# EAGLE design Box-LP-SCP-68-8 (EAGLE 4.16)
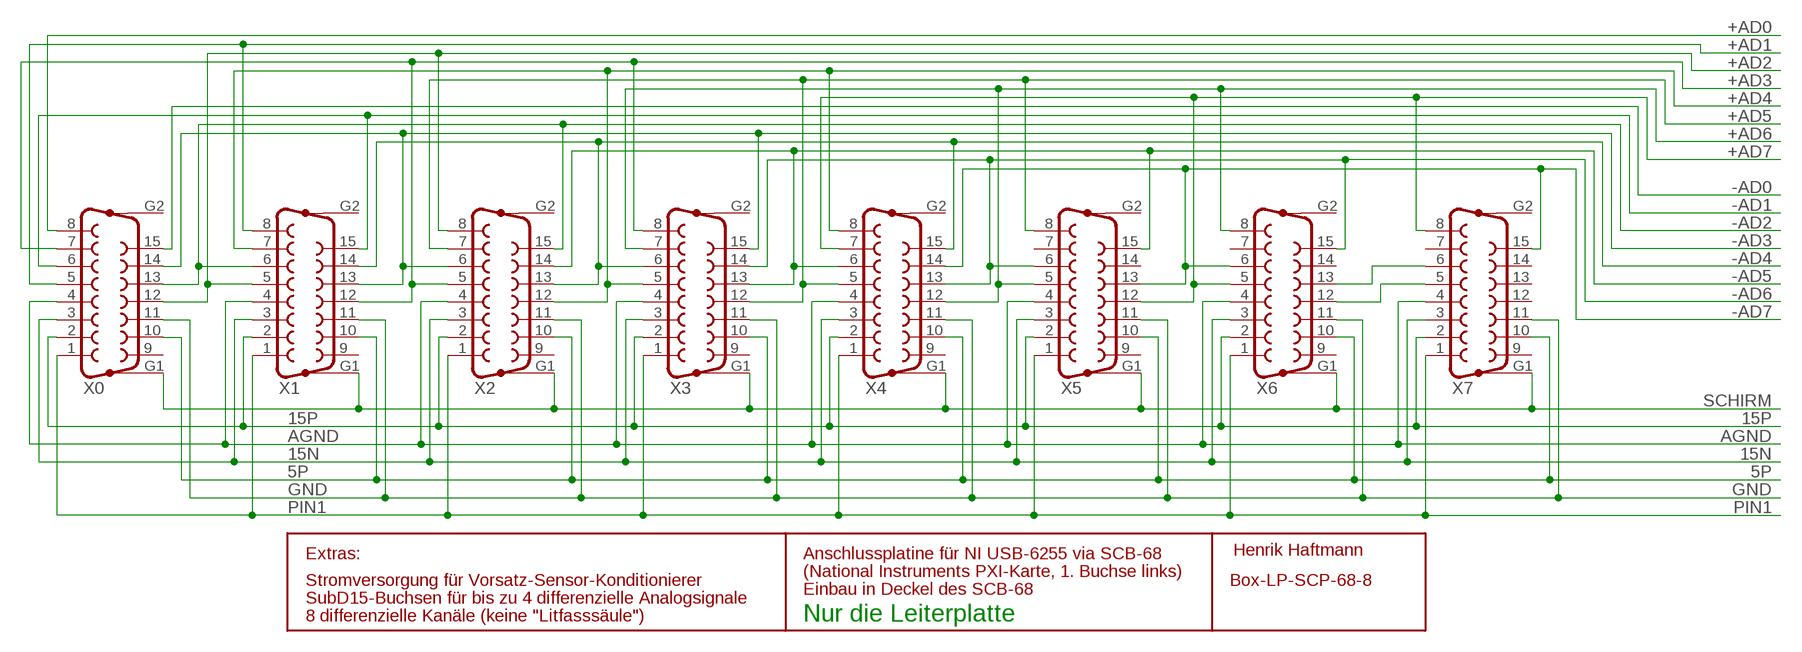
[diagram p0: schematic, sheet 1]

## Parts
X0  F15VP  [F15VP]
X1  F15VP  [F15VP]
X2  F15VP  [F15VP]
X3  F15VP  [F15VP]
X4  F15VP  [F15VP]
X5  F15VP  [F15VP]
X6  F15VP  [F15VP]
X7  F15VP  [F15VP]

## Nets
5P: X0.10 X1.10 X2.10 X3.10 X4.10 X5.10 X6.10 X7.10
15N: X0.3 X1.3 X2.3 X3.3 X4.3 X5.3 X6.3 X7.3
15P: X0.2 X1.2 X2.2 X3.2 X4.2 X5.2 X6.2 X7.2
+AD0: X0.8
+AD1: X0.5 X1.8
+AD2: X0.12 X1.5 X2.8
+AD3: X0.7 X1.12 X2.5 X3.8
+AD4: X1.7 X2.12 X3.5 X4.8
+AD5: X2.7 X3.12 X4.5 X5.8
+AD6: X3.7 X4.12 X5.5 X6.8
+AD7: X4.7 X5.12 X6.5 X7.8
+AD8: X6.12 X7.5
-AD0: X0.15
-AD1: X0.6 X1.15
-AD2: X0.13 X1.6 X2.15
-AD3: X0.14 X1.13 X2.6 X3.15
-AD4: X1.14 X2.13 X3.6 X4.15
-AD5: X2.14 X3.13 X4.6 X5.15
-AD6: X3.14 X4.13 X5.6 X6.15
-AD7: X4.14 X5.13 X6.6 X7.15
AGND: X0.4 X1.4 X2.4 X3.4 X4.4 X5.4 X6.4 X7.4
GND: X0.11 X1.11 X2.11 X3.11 X4.11 X5.11 X6.11 X7.11
N$1: X6.13 X7.6
PIN1: X0.1 X1.1 X2.1 X3.1 X4.1 X5.1 X6.1 X7.1
SCHIRM: X0.G1 X1.G1 X2.G1 X3.G1 X4.G1 X5.G1 X6.G1 X7.G1
Unconnected: X0.9 X0.G2 X1.9 X1.G2 X2.9 X2.G2 X3.9 X3.G2 X4.9 X4.G2 X5.7 X5.9 X5.14 X5.G2 X6.7 X6.9 X6.14 X6.G2 X7.7 X7.9 X7.12 X7.13 X7.14 X7.G2

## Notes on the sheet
- Extras: | Anschlussplatine für NI USB-6255 via SCB-68 | Henrik Haftmann
- (National Instruments PXI-Karte, 1. Buchse links)
- Stromversorgung für Vorsatz-Sensor-Konditionierer
- Einbau in Deckel des SCB-68
- SubD15-Buchsen für bis zu 4 differenzielle Analogsignale
- 8 differenzielle Kanäle (keine "Litfasssäule") | Nur die Leiterplatte

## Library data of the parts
X0 X1-X7 = con-subd:F15VP: SUB-D

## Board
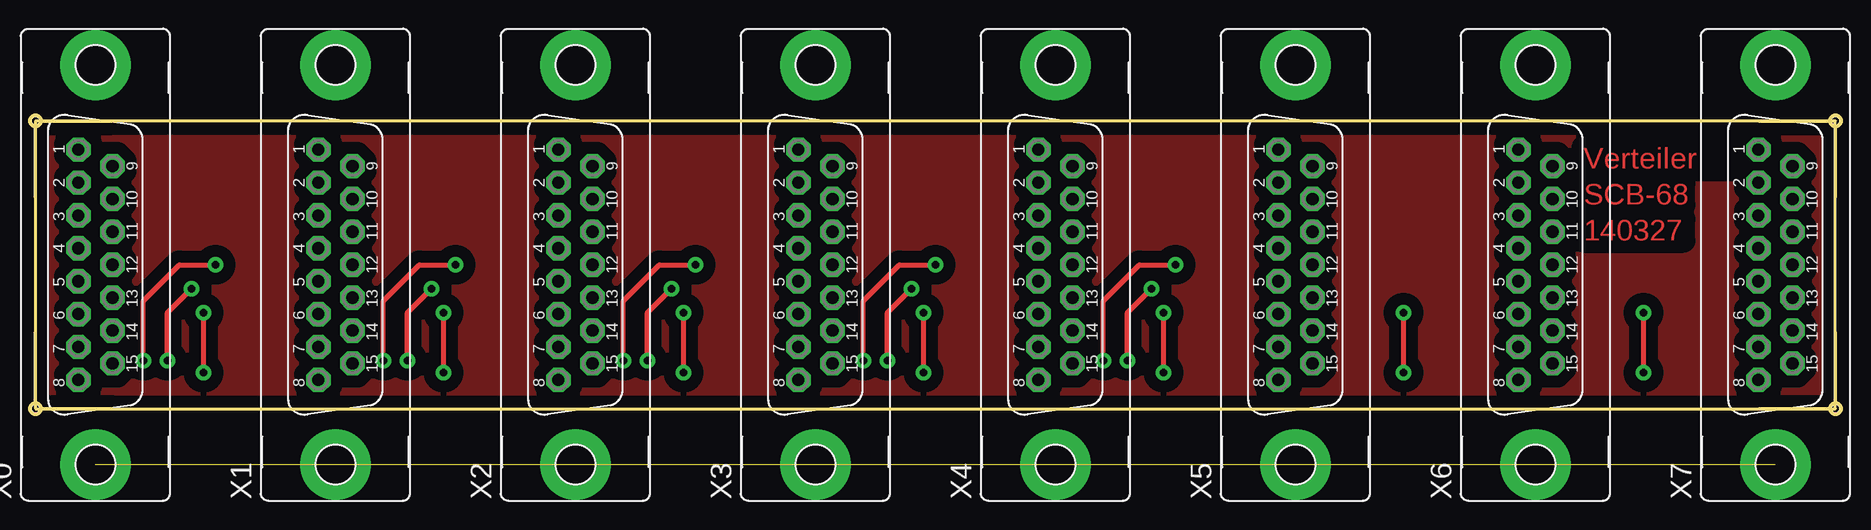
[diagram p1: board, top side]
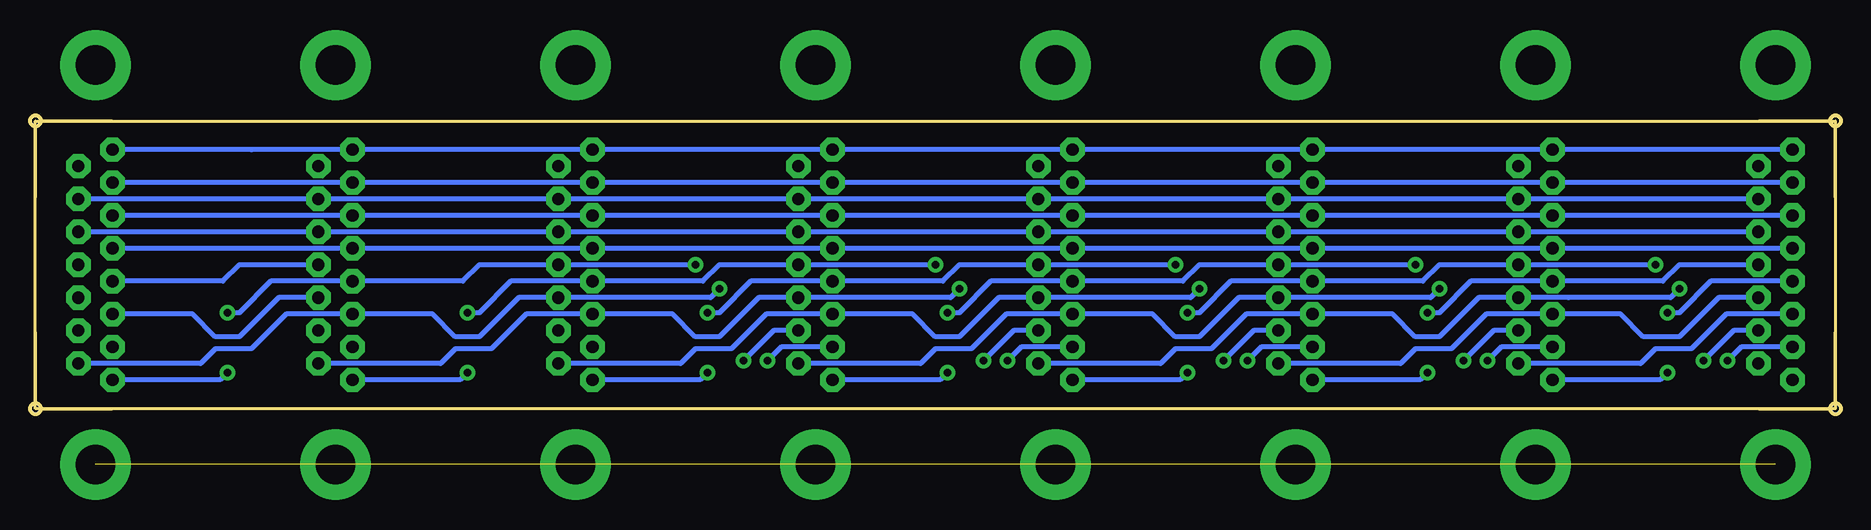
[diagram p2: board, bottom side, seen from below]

Size 150.91 x 24.91 mm. Coordinates in mm from the lower left corner, seen from the top.
Outline: 0.45,0.45 150.45,0.45 150.45,24.45 0.45,24.45 0.45,0.45
Copper layers (1*16): Top 0.035mm / dielectric 1.5mm / Bottom 0.035mm
Design rules "Felber": minimum track width 0.15mm, minimum drill 0.3mm, track to track 0.15mm, track to pad 0.15mm, pad to pad 0.15mm, via to via 0.15mm, smd to smd 0mil, copper to edge 0.3mm, drill to drill 0.3mm, minimum pad ring 10mil, minimum via ring 8mil, stop-mask expansion 4mil, vias tented up to drill 0mil, thermal gap 10mil

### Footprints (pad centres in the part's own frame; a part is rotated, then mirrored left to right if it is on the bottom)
AUSRICHTER = hole 0.6: 0,0
F15VP = drill 1.016 octagon: 1 9.601,1.422; 2 6.858,1.422; 3 4.115,1.422; 4 1.372,1.422; 5 -1.372,1.422; 6 -4.115,1.422; 7 -6.858,1.422; 8 -9.601,1.422; 9 8.23,-1.422; 10 5.486,-1.422; 11 2.743,-1.422; 12 0,-1.422; 13 -2.743,-1.422; 14 -5.486,-1.422; 15 -8.23,-1.422 | drill 3.302 pad 5.08 round: G1 -16.662,0; G2 16.662,0

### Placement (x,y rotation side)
U$1  [AUSRICHTER]  0.45,0.45 0 top
U$2  [AUSRICHTER]  150.45,0.45 90 top
U$3  [AUSRICHTER]  150.45,24.45 180 top
U$4  [AUSRICHTER]  0.45,24.45 270 top
X0  5.45,12.45 90 top
X1  25.45,12.45 90 top
X2  45.45,12.45 90 top
X3  65.45,12.45 90 top
X4  85.45,12.45 90 top
X5  105.45,12.45 90 top
X6  125.45,12.45 90 top
X7  145.45,12.45 90 top

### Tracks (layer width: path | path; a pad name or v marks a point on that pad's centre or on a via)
5P
  Bottom 0.406: X0.10 X1.10 X2.10 X3.10 77.45,17.94 X4.10 X5.10 X6.10 X7.10
15N
  Bottom 0.406: X0.3 21.45,16.57 X1.3 X2.3 X3.3 X4.3 X5.3 X6.3 X7.3
15P
  Bottom 0.406: X0.2 19.43,19.31 X1.2 X2.2 X3.2 X4.2 X5.2 X6.2 X7.2
+AD1  (via drill 0.6 pad 1.27)
  Top 0.406: v14.45,8.45 v14.45,3.45
  Bottom 0.406: X0.5 10.83,11.08 13.45,8.45 v14.45,8.45 | X1.8 15.06,2.85 v14.45,3.45
+AD2  (via drill 0.6 pad 1.27)
  Top 0.406: v34.45,8.45 v34.45,3.45
  Bottom 0.406: X0.12 13.45,12.45 14.83,11.08 X1.5 30.83,11.08 33.45,8.45 v34.45,8.45 | X2.8 35.06,2.85 v34.45,3.45
+AD3  (via drill 0.6 pad 1.27)
  Top 0.406: v54.45,8.45 v54.45,3.45 | v9.45,4.45 9.45,9.45 12.45,12.45 v15.45,12.45
  Bottom 0.406: v54.45,8.45 53.45,8.45 50.83,11.08 X2.5 34.83,11.08 33.45,12.45 X1.12 v15.45,12.45 | X3.8 55.06,2.85 v54.45,3.45 | X0.7 8.31,5.6 v9.45,4.45
+AD4  (via drill 0.6 pad 1.27)
  Top 0.406: v74.45,8.45 v74.45,3.45 | v29.45,4.45 29.45,9.45 32.45,12.45 v35.45,12.45
  Bottom 0.406: v74.45,8.45 73.45,8.45 70.83,11.08 X3.5 54.83,11.08 53.45,12.45 X2.12 v35.45,12.45 | X4.8 75.06,2.85 v74.45,3.45 | X1.7 28.31,5.6 v29.45,4.45
+AD5  (via drill 0.6 pad 1.27)
  Top 0.406: v94.45,8.45 v94.45,3.45 | v55.45,12.45 52.45,12.45 49.45,9.45 v49.45,4.45
  Bottom 0.406: v94.45,8.45 93.45,8.45 90.83,11.08 X4.5 74.83,11.08 73.45,12.45 X3.12 v55.45,12.45 | X5.8 95.06,2.85 v94.45,3.45 | X2.7 48.31,5.6 v49.45,4.45
+AD6  (via drill 0.6 pad 1.27)
  Top 0.406: v114.45,8.45 v114.45,3.45 | v69.45,4.45 69.45,9.45 72.45,12.45 v75.45,12.45
  Bottom 0.406: v114.45,8.45 113.45,8.45 110.83,11.08 X5.5 94.83,11.08 93.45,12.45 X4.12 v75.45,12.45 | X6.8 115.06,2.85 v114.45,3.45 | X3.7 68.31,5.6 v69.45,4.45
+AD7  (via drill 0.6 pad 1.27)
  Top 0.406: v134.45,8.45 v134.45,3.45 | v89.45,4.45 89.45,9.45 92.45,12.45 v95.45,12.45
  Bottom 0.406: v134.45,8.45 133.45,8.45 130.83,11.08 X6.5 114.83,11.08 113.45,12.45 X5.12 v95.45,12.45 | X7.8 135.06,2.85 v134.45,3.45 | X4.7 88.31,5.6 v89.45,4.45
+AD8
  Bottom 0.406: X6.12 133.45,12.45 134.83,11.08 X7.5
-AD1
  Bottom 0.406: X0.6 9.57,8.34 12.45,5.45 15.45,5.45 16.68,4.22 X1.15
-AD2
  Bottom 0.406: X0.13 10.2,9.71 13.45,6.45 16.45,6.45 18.34,8.34 X1.6 29.57,8.34 32.45,5.45 35.45,5.45 36.68,4.22 X2.15
-AD3  (via drill 0.6 pad 1.27)
  Top 0.406: v11.45,4.45 11.45,8.45 v13.45,10.45
  Bottom 0.406: X3.15 56.68,4.22 55.45,5.45 52.45,5.45 49.57,8.34 X2.6 37.34,8.34 35.45,6.45 33.45,6.45 30.2,9.71 X1.13 22.71,9.71 14.2,9.71 v13.45,10.45 | X0.14 8.94,6.97 v11.45,4.45
-AD4  (via drill 0.6 pad 1.27)
  Top 0.406: v31.45,4.45 31.45,8.45 v33.45,10.45
  Bottom 0.406: X4.15 76.68,4.22 75.45,5.45 72.45,5.45 69.57,8.34 X3.6 57.34,8.34 55.45,6.45 53.45,6.45 50.2,9.71 X2.13 34.2,9.71 v33.45,10.45 | X1.14 28.94,6.97 v31.45,4.45
-AD5  (via drill 0.6 pad 1.27)
  Top 0.406: v51.45,4.45 51.45,8.45 v53.45,10.45
  Bottom 0.406: X5.15 96.68,4.22 95.45,5.45 92.45,5.45 89.57,8.34 X4.6 77.34,8.34 75.45,6.45 73.45,6.45 70.2,9.71 X3.13 54.2,9.71 v53.45,10.45 | X2.14 48.94,6.97 v51.45,4.45
-AD6  (via drill 0.6 pad 1.27)
  Top 0.406: v71.45,4.45 71.45,8.45 v73.45,10.45
  Bottom 0.406: X6.15 116.68,4.22 115.45,5.45 112.45,5.45 109.57,8.34 X5.6 97.34,8.34 95.45,6.45 93.45,6.45 90.2,9.71 X4.13 74.2,9.71 v73.45,10.45 | X3.14 68.94,6.97 v71.45,4.45
-AD7  (via drill 0.6 pad 1.27)
  Top 0.406: v91.45,4.45 91.45,8.45 v93.45,10.45
  Bottom 0.406: X7.15 136.68,4.22 135.45,5.45 132.45,5.45 129.57,8.34 X6.6 117.34,8.34 115.45,6.45 113.45,6.45 110.2,9.71 X5.13 94.2,9.71 v93.45,10.45 | X4.14 88.94,6.97 v91.45,4.45
AGND
  Bottom 0.406: X0.4 20.09,13.83 X1.4 X2.4 X3.4 X4.4 X5.4 X6.4 X7.4
GND
  Bottom 0.406: X0.11 X1.11 X2.11 X3.11 X4.11 97.46,15.2 X5.11 X6.11 X7.11
N$1
  Bottom 0.406: X6.13 130.2,9.71 133.45,6.45 135.45,6.45 137.34,8.34 X7.6
PIN1
  Bottom 0.406: X0.1 X1.1 X2.1 X3.1 X4.1 X5.1 X6.1 132.45,22.06 X7.1
SCHIRM  (7 unrouted)
  pour Top (isolate 1): 1.45,23.45 149.45,23.45 149.45,1.45 1.45,1.45

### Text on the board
Top: Verteiler | SCB-68 | 140327
Measures: 24 | 150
